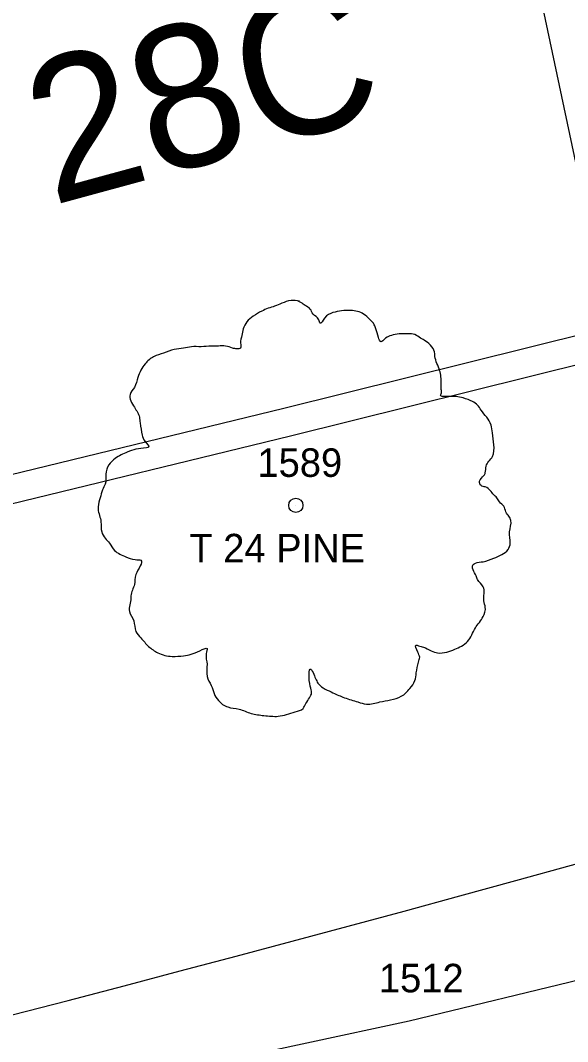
# Model space of a CAD drawing. Extents: x 1964982 to 1970452, y 1116335 to 1119906.
# Drawn here: x 1966657.67 to 1966676.88, y 1117427.62 to 1117463.46 of the extents above; entities that cross this region are included whole.
import ezdxf

# ---------------------------------------------------------------- set-up
doc = ezdxf.new("R2010")
doc.units = 0
for name, color, linetype in [('RD_EX_Road', 7, 'Continuous'), ('RD_EX_Road_txCode', 7, 'Continuous'), ('RD_EX_RW', 7, 'Continuous'), ('RD_EX_VEG', 7, 'Continuous'), ('RD_EX_VEG_txCode', 7, 'Continuous'), ('RD_HC_CL_Rel', 7, 'Continuous'), ('RD_HC_Data', 7, 'Continuous'), ('RD_PD_CstnLmt', 7, 'Continuous'), ('RD_PD_Final_TrvlWay', 7, 'Continuous'), ('RD_PD_RW', 7, 'Continuous'), ('RD_PD_TX_CstnLmt', 7, 'Continuous'), ('RD_SMD_Locator', 7, 'Continuous')]:
    doc.layers.add(name, color=color, linetype=linetype)

msp = doc.modelspace()

# ---------------------------------------------------------------- linework, layer by layer
at = {"layer": 'RD_EX_Road'}
msp.add_lwpolyline([(1966297.245, 1117343.102), (1966344.085, 1117357.038), (1966390.785, 1117368.561), (1966438.122, 1117379.082), (1966484.547, 1117389.131), (1966531.199, 1117398.733), (1966578.388, 1117408.593), (1966604.527, 1117414.058), (1966624.537, 1117418.323), (1966671.319, 1117428.348), (1966716.506, 1117439.32), (1966736.604, 1117445.59), (1966754.133, 1117451.442), (1966759.658, 1117453.517), (1966769.512, 1117457.475)], dxfattribs=at)
at = {"layer": 'RD_EX_RW'}
msp.add_lwpolyline([(1966297.245, 1117343.102), (1966344.085, 1117357.038), (1966390.785, 1117368.561), (1966438.122, 1117379.082), (1966484.547, 1117389.131), (1966531.199, 1117398.733), (1966578.388, 1117408.593), (1966604.527, 1117414.058), (1966624.537, 1117418.323), (1966671.319, 1117428.348), (1966716.506, 1117439.32), (1966736.604, 1117445.59), (1966754.133, 1117451.442), (1966759.658, 1117453.517), (1966769.512, 1117457.475)], dxfattribs=at)
at = {"layer": 'RD_EX_VEG'}
for centre, radius in [((1966667.339, 1117446.441), 0.25), ((1966667.339, 1117446.441), 0.25), ((1966667.326, 1117446.422), 0.0001), ((1966667.326, 1117446.422), 0.0001)]:
    msp.add_circle(centre, radius, dxfattribs=at)
for points in [[(1966667.471, 1117453.608), (1966667.171, 1117453.633), (1966666.846, 1117453.533), (1966666.596, 1117453.433), (1966666.371, 1117453.358), (1966666.146, 1117453.258), (1966665.846, 1117453.083), (1966665.622, 1117452.883), (1966665.497, 1117452.634), (1966665.447, 1117452.409), (1966665.397, 1117452.134), (1966665.397, 1117451.959), (1966665.272, 1117451.934), (1966665.122, 1117451.959), (1966664.872, 1117452.034), (1966664.622, 1117452.034), (1966664.372, 1117452.034), (1966664.022, 1117452.009), (1966663.672, 1117452.009), (1966663.398, 1117451.959), (1966663.073, 1117451.909), (1966662.698, 1117451.784), (1966662.348, 1117451.659), (1966662.048, 1117451.409), (1966661.798, 1117450.934), (1966661.673, 1117450.584), (1966661.523, 1117450.335), (1966661.673, 1117449.885), (1966661.848, 1117449.535), (1966661.873, 1117449.335), (1966661.948, 1117448.91), (1966662.048, 1117448.685), (1966662.173, 1117448.485), (1966662.098, 1117448.46), (1966661.723, 1117448.41), (1966661.423, 1117448.31), (1966660.999, 1117448.086), (1966660.774, 1117447.861), (1966660.674, 1117447.536), (1966660.649, 1117447.186), (1966660.549, 1117446.986), (1966660.474, 1117446.711), (1966660.449, 1117446.636), (1966660.399, 1117446.311), (1966660.499, 1117445.861), (1966660.524, 1117445.512), (1966660.649, 1117445.287), (1966660.799, 1117445.112), (1966660.974, 1117444.862), (1966661.373, 1117444.637), (1966661.698, 1117444.537), (1966661.898, 1117444.512), (1966661.723, 1117444.012), (1966661.673, 1117443.662), (1966661.548, 1117443.263), (1966661.548, 1117443.188), (1966661.498, 1117442.713), (1966661.648, 1117442.388), (1966661.723, 1117442.013), (1966661.898, 1117441.788), (1966662.173, 1117441.488), (1966662.498, 1117441.264), (1966662.998, 1117441.139), (1966663.398, 1117441.164), (1966663.972, 1117441.338), (1966664.222, 1117441.413), (1966664.197, 1117441.239), (1966664.222, 1117440.864), (1966664.222, 1117440.439), (1966664.372, 1117440.114), (1966664.472, 1117439.839), (1966664.622, 1117439.589), (1966664.947, 1117439.364), (1966665.347, 1117439.289), (1966665.771, 1117439.139), (1966666.221, 1117439.064), (1966666.721, 1117439.039), (1966667.321, 1117439.189), (1966667.596, 1117439.314), (1966667.696, 1117439.489), (1966667.896, 1117439.864), (1966667.846, 1117440.089), (1966667.871, 1117440.689), (1966667.97, 1117440.514), (1966668.145, 1117440.164), (1966668.645, 1117439.864), (1966669.045, 1117439.689), (1966669.52, 1117439.539), (1966669.82, 1117439.464), (1966670.294, 1117439.539), (1966670.669, 1117439.614), (1966671.044, 1117439.739), (1966671.344, 1117440.014), (1966671.519, 1117440.289), (1966671.569, 1117440.564), (1966671.644, 1117440.939), (1966671.694, 1117441.114)], [(1966667.471, 1117453.608), (1966667.171, 1117453.633), (1966666.846, 1117453.533), (1966666.596, 1117453.433), (1966666.371, 1117453.358), (1966666.146, 1117453.258), (1966665.846, 1117453.083), (1966665.622, 1117452.883), (1966665.497, 1117452.634), (1966665.447, 1117452.409), (1966665.397, 1117452.134), (1966665.397, 1117451.959), (1966665.272, 1117451.934), (1966665.122, 1117451.959), (1966664.872, 1117452.034), (1966664.622, 1117452.034), (1966664.372, 1117452.034), (1966664.022, 1117452.009), (1966663.672, 1117452.009), (1966663.398, 1117451.959), (1966663.073, 1117451.909), (1966662.698, 1117451.784), (1966662.348, 1117451.659), (1966662.048, 1117451.409), (1966661.798, 1117450.934), (1966661.673, 1117450.584), (1966661.523, 1117450.335), (1966661.673, 1117449.885), (1966661.848, 1117449.535), (1966661.873, 1117449.335), (1966661.948, 1117448.91), (1966662.048, 1117448.685), (1966662.173, 1117448.485), (1966662.098, 1117448.46), (1966661.723, 1117448.41), (1966661.423, 1117448.31), (1966660.999, 1117448.086), (1966660.774, 1117447.861), (1966660.674, 1117447.536), (1966660.649, 1117447.186), (1966660.549, 1117446.986), (1966660.474, 1117446.711), (1966660.449, 1117446.636), (1966660.399, 1117446.311), (1966660.499, 1117445.861), (1966660.524, 1117445.512), (1966660.649, 1117445.287), (1966660.799, 1117445.112), (1966660.974, 1117444.862), (1966661.373, 1117444.637), (1966661.698, 1117444.537), (1966661.898, 1117444.512), (1966661.723, 1117444.012), (1966661.673, 1117443.662), (1966661.548, 1117443.263), (1966661.548, 1117443.188), (1966661.498, 1117442.713), (1966661.648, 1117442.388), (1966661.723, 1117442.013), (1966661.898, 1117441.788), (1966662.173, 1117441.488), (1966662.498, 1117441.264), (1966662.998, 1117441.139), (1966663.398, 1117441.164), (1966663.972, 1117441.338), (1966664.222, 1117441.413), (1966664.197, 1117441.239), (1966664.222, 1117440.864), (1966664.222, 1117440.439), (1966664.372, 1117440.114), (1966664.472, 1117439.839), (1966664.622, 1117439.589), (1966664.947, 1117439.364), (1966665.347, 1117439.289), (1966665.771, 1117439.139), (1966666.221, 1117439.064), (1966666.721, 1117439.039), (1966667.321, 1117439.189), (1966667.596, 1117439.314), (1966667.696, 1117439.489), (1966667.896, 1117439.864), (1966667.846, 1117440.089), (1966667.871, 1117440.689), (1966667.97, 1117440.514), (1966668.145, 1117440.164), (1966668.645, 1117439.864), (1966669.045, 1117439.689), (1966669.52, 1117439.539), (1966669.82, 1117439.464), (1966670.294, 1117439.539), (1966670.669, 1117439.614), (1966671.044, 1117439.739), (1966671.344, 1117440.014), (1966671.519, 1117440.289), (1966671.569, 1117440.564), (1966671.644, 1117440.939), (1966671.694, 1117441.114)], [(1966671.694, 1117441.114), (1966671.619, 1117441.289), (1966671.569, 1117441.538), (1966671.644, 1117441.513), (1966671.819, 1117441.463), (1966672.094, 1117441.338), (1966672.319, 1117441.264), (1966672.643, 1117441.289), (1966672.918, 1117441.388), (1966673.368, 1117441.663), (1966673.643, 1117442.138), (1966673.918, 1117442.538), (1966673.993, 1117442.863), (1966673.943, 1117443.088), (1966673.918, 1117443.587), (1966673.718, 1117443.837), (1966673.668, 1117443.962), (1966673.568, 1117444.362), (1966673.643, 1117444.412), (1966673.918, 1117444.462), (1966674.293, 1117444.587), (1966674.568, 1117444.712), (1966674.793, 1117444.887), (1966674.867, 1117445.112), (1966674.843, 1117445.512), (1966674.892, 1117445.911), (1966674.818, 1117446.061), (1966674.718, 1117446.211), (1966674.643, 1117446.411), (1966674.493, 1117446.561), (1966674.393, 1117446.711), (1966674.293, 1117446.811), (1966674.168, 1117446.961), (1966673.993, 1117447.086), (1966673.843, 1117447.136), (1966673.793, 1117447.286), (1966673.943, 1117447.486), (1966673.993, 1117447.586), (1966674.018, 1117447.811), (1966674.243, 1117448.16), (1966674.293, 1117448.56), (1966674.243, 1117448.985), (1966674.193, 1117449.26), (1966674.043, 1117449.535), (1966673.843, 1117449.785), (1966673.718, 1117449.96), (1966673.543, 1117450.085), (1966673.218, 1117450.21), (1966672.968, 1117450.26), (1966672.618, 1117450.26), (1966672.419, 1117450.31), (1966672.444, 1117450.36), (1966672.444, 1117450.509), (1966672.444, 1117450.784), (1966672.369, 1117451.234), (1966672.219, 1117451.734), (1966672.219, 1117451.759), (1966672.119, 1117452.009), (1966671.894, 1117452.209), (1966671.719, 1117452.309), (1966671.519, 1117452.434), (1966671.269, 1117452.459), (1966670.969, 1117452.459), (1966670.694, 1117452.409), (1966670.494, 1117452.309), (1966670.319, 1117452.184), (1966670.244, 1117452.334), (1966670.145, 1117452.634), (1966670.095, 1117452.783), (1966669.945, 1117452.958), (1966669.72, 1117453.158), (1966669.27, 1117453.283), (1966668.645, 1117453.208), (1966668.345, 1117453.008), (1966668.195, 1117452.833), (1966668.145, 1117452.958), (1966667.945, 1117453.158), (1966667.846, 1117453.333), (1966667.671, 1117453.458), (1966667.521, 1117453.558), (1966667.421, 1117453.608)], [(1966671.694, 1117441.114), (1966671.619, 1117441.289), (1966671.569, 1117441.538), (1966671.644, 1117441.513), (1966671.819, 1117441.463), (1966672.094, 1117441.338), (1966672.319, 1117441.264), (1966672.643, 1117441.289), (1966672.918, 1117441.388), (1966673.368, 1117441.663), (1966673.643, 1117442.138), (1966673.918, 1117442.538), (1966673.993, 1117442.863), (1966673.943, 1117443.088), (1966673.918, 1117443.587), (1966673.718, 1117443.837), (1966673.668, 1117443.962), (1966673.568, 1117444.362), (1966673.643, 1117444.412), (1966673.918, 1117444.462), (1966674.293, 1117444.587), (1966674.568, 1117444.712), (1966674.793, 1117444.887), (1966674.867, 1117445.112), (1966674.843, 1117445.512), (1966674.892, 1117445.911), (1966674.818, 1117446.061), (1966674.718, 1117446.211), (1966674.643, 1117446.411), (1966674.493, 1117446.561), (1966674.393, 1117446.711), (1966674.293, 1117446.811), (1966674.168, 1117446.961), (1966673.993, 1117447.086), (1966673.843, 1117447.136), (1966673.793, 1117447.286), (1966673.943, 1117447.486), (1966673.993, 1117447.586), (1966674.018, 1117447.811), (1966674.243, 1117448.16), (1966674.293, 1117448.56), (1966674.243, 1117448.985), (1966674.193, 1117449.26), (1966674.043, 1117449.535), (1966673.843, 1117449.785), (1966673.718, 1117449.96), (1966673.543, 1117450.085), (1966673.218, 1117450.21), (1966672.968, 1117450.26), (1966672.618, 1117450.26), (1966672.419, 1117450.31), (1966672.444, 1117450.36), (1966672.444, 1117450.509), (1966672.444, 1117450.784), (1966672.369, 1117451.234), (1966672.219, 1117451.734), (1966672.219, 1117451.759), (1966672.119, 1117452.009), (1966671.894, 1117452.209), (1966671.719, 1117452.309), (1966671.519, 1117452.434), (1966671.269, 1117452.459), (1966670.969, 1117452.459), (1966670.694, 1117452.409), (1966670.494, 1117452.309), (1966670.319, 1117452.184), (1966670.244, 1117452.334), (1966670.145, 1117452.634), (1966670.095, 1117452.783), (1966669.945, 1117452.958), (1966669.72, 1117453.158), (1966669.27, 1117453.283), (1966668.645, 1117453.208), (1966668.345, 1117453.008), (1966668.195, 1117452.833), (1966668.145, 1117452.958), (1966667.945, 1117453.158), (1966667.846, 1117453.333), (1966667.671, 1117453.458), (1966667.521, 1117453.558), (1966667.421, 1117453.608)]]:
    msp.add_spline(points, degree=3, dxfattribs=at)
at = {"layer": 'RD_HC_CL_Rel'}
msp.add_arc((1966373.74, 1118527.456), 1145.915, 281.904723, 295.046328, dxfattribs=at)
at = {"layer": 'RD_HC_Data'}
msp.add_line((1966684.871, 1117421.945), (1966664.447, 1117518.825), dxfattribs=at)
at = {"layer": 'RD_PD_CstnLmt'}
for p, q in [((1966714.573, 1117460.668), (1966667.156, 1117448.875)), ((1966667.156, 1117448.875), (1966619.782, 1117437.316))]:
    msp.add_line(p, q, dxfattribs=at)
at = {"layer": 'RD_PD_Final_TrvlWay'}
for radius in [1134.915, 1156.915]:
    msp.add_arc((1966373.74, 1118527.456), radius, 281.904723, 295.046328, dxfattribs=at)
at = {"layer": 'RD_PD_RW'}
for p, q in [((1966714.309, 1117461.633), (1966666.917, 1117449.846)), ((1966666.917, 1117449.846), (1966619.521, 1117438.281))]:
    msp.add_line(p, q, dxfattribs=at)
at = {"layer": 'RD_SMD_Locator'}
msp.add_circle((1966671.319, 1117428.348), 0.001, dxfattribs=at)
msp.add_circle((1966671.319, 1117428.348), 0.001, dxfattribs=at)

# ---------------------------------------------------------------- texts
at = {"layer": 'RD_EX_Road_txCode'}
msp.add_text('1512', height=1, dxfattribs=at).set_placement((1966670.256, 1117429.348))
msp.add_text('1512', height=1, dxfattribs=at).set_placement((1966670.256, 1117429.348))
at = {"layer": 'RD_EX_VEG_txCode'}
for s, p in [('1589', (1966665.992, 1117447.441)), ('1589', (1966665.992, 1117447.441)), ('T 24 PINE', (1966663.603, 1117444.441)), ('T 24 PINE', (1966663.603, 1117444.441))]:
    msp.add_text(s, height=1, dxfattribs=at).set_placement(p)
at = {"layer": 'RD_PD_TX_CstnLmt'}
msp.add_text('28C', height=5, rotation=15.2184, dxfattribs=at).set_placement((1966658.772, 1117456.958))

doc.saveas('drawing.dxf')
